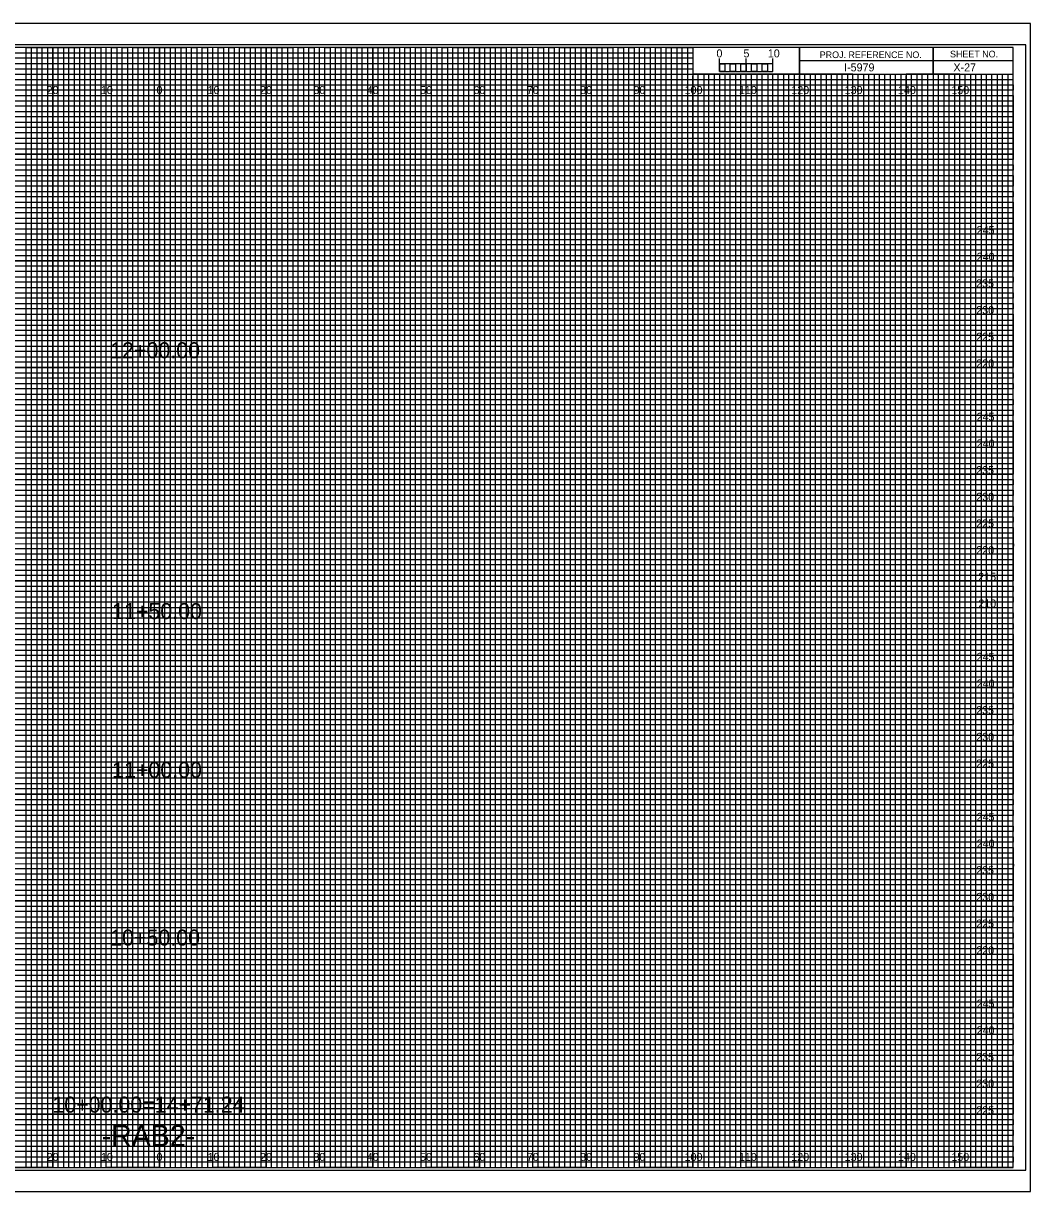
# Model space of a CAD drawing. Extents: x -13 to 323, y -5 to 654.
# Drawn here: x 134.5 to 323.3, y -4.5 to 214.5 of the extents above; entities that cross this region are included whole.
import ezdxf

# ---------------------------------------------------------------- set-up
doc = ezdxf.new("R2010")
doc.units = 0
for name, color, linetype in [('Exist CMT Pavement', 7, 'Continuous'), ('Exist Cross Section Cell', 7, 'Continuous'), ('Exist XS Center Line Elevation Label', 7, 'Continuous'), ('Exist XS Ground Line', 7, 'Continuous'), ('Prop CMT Conc Surface', 7, 'Continuous'), ('Prop CMT Concrete Structures', 7, 'Continuous'), ('Prop CMT DNC', 7, 'Continuous'), ('Prop CMT Pvmt Course 1 CG', 7, 'Continuous'), ('Prop CMT Pvmt Course 1 Wedge', 7, 'Continuous'), ('Prop CMT Pvmt Course 2', 7, 'Continuous'), ('Prop CMT Pvmt Course 2 Wedge', 7, 'Continuous'), ('Prop CMT Pvmt Course 3', 7, 'Continuous'), ('Prop CMT Pvmt Course 3 Wedge', 7, 'Continuous'), ('Prop CMT Pvmt Surface', 7, 'Continuous'), ('Prop CMT Shear Line', 7, 'Continuous'), ('Prop CMT Slope Grass', 7, 'Continuous'), ('Prop CMT Subgrade Earthwork', 7, 'Continuous')]:
    doc.layers.add(name, color=color, linetype=linetype)

msp = doc.modelspace()

# ---------------------------------------------------------------- linework, layer by layer
at = {"layer": 'Exist XS Center Line Elevation Label'}
for points in [[(125, 0), (135, 0), (135, 210), (145, 210), (145, 0), (155, 0), (155, 210), (165, 210), (165, 0), (175, 0), (175, 210), (185, 210), (185, 0), (195, 0), (195, 210), (205, 210), (205, 0), (215, 0), (215, 210), (225, 210), (225, 0), (235, 0), (235, 210), (245, 210), (245, 0), (255, 0), (255, 210), (259.93, 210), (260, 210), (260, 205), (264.99, 205), (264.99, 0), (275, 0), (275, 205), (285, 205), (285, 0), (295, 0), (295, 205), (305, 205), (305, 0), (315, 0), (315, 205)], [(0, 205), (275, 205)], [(0, 185), (320, 185), (320, 195), (0, 195)], [(0, 165), (320, 165), (320, 175), (0, 175)], [(0, 145), (320, 145), (320, 155), (0, 155)], [(0, 125), (320, 125), (320, 135), (0, 135)], [(0, 105), (320, 105), (320, 115), (0, 115)], [(0, 85), (320, 85), (320, 95), (0, 95)], [(0, 65), (320, 65), (320, 75), (0, 75)], [(0, 45), (320, 45), (320, 55), (0, 55)], [(0, 25), (320, 25), (320, 35), (0, 35)], [(0, 5), (320, 5), (320, 15), (0, 15)]]:
    msp.add_lwpolyline(points, dxfattribs=at)
at = {"layer": 'Exist XS Ground Line'}
for p, q in [((150, 210), (140, 210)), ((140, 210), (140, 0)), ((150, 0), (150, 210)), ((170, 210), (160, 210)), ((160, 210), (160, 0)), ((170, 0), (170, 210)), ((190, 210), (180, 210)), ((180, 210), (180, 0)), ((190, 0), (190, 210)), ((210, 210), (200, 210)), ((200, 210), (200, 0)), ((210, 0), (210, 210)), ((230, 210), (220, 210)), ((220, 210), (220, 0)), ((230, 0), (230, 210)), ((250, 210), (240, 210)), ((240, 210), (240, 0)), ((250, 0), (250, 210)), ((260, 210), (260, 0)), ((270, 0), (270, 205)), ((290, 205), (280, 205)), ((280, 205), (280, 0)), ((290, 0), (290, 205)), ((310, 205), (300, 205)), ((300, 205), (300, 0)), ((310, 0), (310, 205)), ((140, 0), (130, 0)), ((160, 0), (150, 0)), ((180, 0), (170, 0)), ((200, 0), (190, 0)), ((220, 0), (210, 0)), ((240, 0), (230, 0)), ((260, 0), (250, 0)), ((280, 0), (270, 0)), ((300, 0), (290, 0)), ((320, 0), (310, 0)), ((320, 0), (320, 0))]:
    msp.add_line(p, q, dxfattribs=at)
for points in [[(0, 200), (320, 200), (320, 190), (0, 190)], [(0, 180), (320, 180), (320, 170), (0, 170)], [(0, 160), (320, 160), (320, 150), (0, 150)], [(0, 140), (320, 140), (320, 130), (0, 130)], [(0, 120), (320, 120), (320, 110), (0, 110)], [(0, 100), (320, 100), (320, 90), (0, 90)], [(0, 80), (320, 80), (320, 70), (0, 70)], [(0, 60), (320, 60), (320, 50), (0, 50)], [(0, 40), (320, 40), (320, 30), (0, 30)], [(0, 20), (320, 20), (320, 10), (0, 10)]]:
    msp.add_lwpolyline(points, dxfattribs=at)
at = {"layer": 'Prop CMT Conc Surface'}
msp.add_lwpolyline([(-13.4, -4.5), (323.3, -4.5), (323.3, 214.5), (-13.4, 214.5)], close=True, dxfattribs=at)
at = {"layer": 'Prop CMT Concrete Structures'}
for p, q in [((305, 210), (305, 205)), ((305, 205), (305, 210)), ((280, 207.5), (280, 205)), ((320, 207.49), (280, 207.49)), ((280, 205), (320, 205))]:
    msp.add_line(p, q, dxfattribs=at)
for points in [[(320, 210), (0, 210), (0, 0), (320, 0)], [(280, 210), (260, 210), (260, 205.03), (280, 205.03)], [(320, 210), (280, 210), (280, 205), (320, 205)]]:
    msp.add_lwpolyline(points, close=True, dxfattribs=at)
at = {"layer": 'Prop CMT DNC'}
for p, q in [((267, 205), (266.01, 205)), ((266.01, 205), (266.01, 0)), ((267, 0), (267, 205)), ((269, 205), (268, 205)), ((268, 205), (268, 0)), ((269, 0), (269, 205)), ((266.01, 0), (265, 0)), ((268, 0), (267, 0))]:
    msp.add_line(p, q, dxfattribs=at)
for points in [[(135, 0), (136, 0), (136, 210), (137, 210), (137, 0)], [(137, 0), (138, 0), (138, 210), (139, 210), (139, 0)], [(140, 0), (141, 0), (141, 210), (142, 210), (142, 0)], [(142, 0), (143, 0), (143, 210), (144, 210), (144, 0)], [(145, 0), (146, 0), (146, 210), (147, 210), (147, 0)], [(147, 0), (148, 0), (148, 210), (149, 210), (149, 0)], [(150, 0), (151, 0), (151, 210), (152, 210), (152, 0)], [(152, 0), (153, 0), (153, 210), (154, 210), (154, 0)], [(155, 0), (156, 0), (156, 210), (157, 210), (157, 0)], [(157, 0), (158, 0), (158, 210), (159, 210), (159, 0)], [(160, 0), (161, 0), (161, 210), (162, 210), (162, 0)], [(162, 0), (163, 0), (163, 210), (164, 210), (164, 0)], [(165, 0), (166, 0), (166, 210), (167, 210), (167, 0)], [(167, 0), (168, 0), (168, 210), (169, 210), (169, 0)], [(170, 0), (171, 0), (171, 210), (172, 210), (172, 0)], [(172, 0), (173, 0), (173, 210), (174, 210), (174, 0)], [(175, 0), (176, 0), (176, 210), (177, 210), (177, 0)], [(177, 0), (178, 0), (178, 210), (179, 210), (179, 0)], [(180, 0), (181, 0), (181, 210), (182, 210), (182, 0)], [(182, 0), (183, 0), (183, 210), (184, 210), (184, 0)], [(185, 0), (186, 0), (186, 210), (187, 210), (187, 0)], [(187, 0), (188, 0), (188, 210), (189, 210), (189, 0)], [(190, 0), (191, 0), (191, 210), (192, 210), (192, 0)], [(192, 0), (193, 0), (193, 210), (194, 210), (194, 0)], [(195, 0), (196, 0), (196, 210), (197, 210), (197, 0)], [(197, 0), (198, 0), (198, 210), (199, 210), (199, 0)], [(200, 0), (201, 0), (201, 210), (202, 210), (202, 0)], [(202, 0), (203, 0), (203, 210), (204, 210), (204, 0)], [(205, 0), (206, 0), (206, 210), (207, 210), (207, 0)], [(207, 0), (208, 0), (208, 210), (209, 210), (209, 0)], [(210, 0), (211, 0), (211, 210), (212, 210), (212, 0)], [(212, 0), (213, 0), (213, 210), (214, 210), (214, 0)], [(215, 0), (216, 0), (216, 210), (217, 210), (217, 0)], [(217, 0), (218, 0), (218, 210), (219, 210), (219, 0)], [(220, 0), (221, 0), (221, 210), (222, 210), (222, 0)], [(222, 0), (223, 0), (223, 210), (224, 210), (224, 0)], [(225, 0), (226, 0), (226, 210), (227, 210), (227, 0)], [(227, 0), (228, 0), (228, 210), (229, 210), (229, 0)], [(230, 0), (231, 0), (231, 210), (232, 210), (232, 0)], [(232, 0), (233, 0), (233, 210), (234, 210), (234, 0)], [(235, 0), (236, 0), (236, 210), (237, 210), (237, 0)], [(237, 0), (238, 0), (238, 210), (239, 210), (239, 0)], [(240, 0), (241, 0), (241, 210), (242, 210), (242, 0)], [(242, 0), (243, 0), (243, 210), (244, 210), (244, 0)], [(245, 0), (246, 0), (246, 210), (247, 210), (247, 0)], [(247, 0), (248, 0), (248, 210), (249, 210), (249, 0)], [(250, 0), (251, 0), (251, 210), (252, 210), (252, 0)], [(252, 0), (253, 0), (253, 210), (254, 210), (254, 0)], [(255, 0), (256, 0), (256, 210), (257, 210), (257, 0)], [(257, 0), (258, 0), (258, 210), (259, 210), (259, 0)], [(260, 0), (261, 0), (261, 205), (262.02, 205), (262.02, 0)], [(262, 0), (263, 0), (263, 205), (263.99, 205), (263.99, 0)], [(270, 0), (270.98, 0), (270.98, 205), (272, 205), (272, 0)], [(272, 0), (273, 0), (273, 205), (274.05, 205), (274.05, 0)], [(275, 0), (276, 0), (276, 205), (277, 205), (277, 0)], [(277, 0), (278, 0), (278, 205), (279, 205), (279, 0)], [(280, 0), (281, 0), (281, 205), (282, 205), (282, 0)], [(282, 0), (283, 0), (283, 205), (284, 205), (284, 0)], [(285, 0), (286, 0), (286, 205), (287, 205), (287, 0)], [(287, 0), (288, 0), (288, 205), (289, 205), (289, 0)], [(290, 0), (291, 0), (291, 205), (292, 205), (292, 0)], [(292, 0), (293, 0), (293, 205), (294, 205), (294, 0)], [(295, 0), (296, 0), (296, 205), (297, 205), (297, 0)], [(297, 0), (298, 0), (298, 205), (299, 205), (299, 0)], [(300, 0), (301, 0), (301, 205), (302, 205), (302, 0)], [(302, 0), (303, 0), (303, 205), (304, 205), (304, 0)], [(305, 0), (306, 0), (306, 205), (307, 205), (307, 0)], [(307, 0), (308, 0), (308, 205), (309, 205), (309, 0)], [(310, 0), (311, 0), (311, 205), (312, 205), (312, 0)], [(312, 0), (313, 0), (313, 205), (314, 205), (314, 0)], [(315, 0), (316, 0), (316, 205), (317, 205), (317, 0)], [(317, 0), (318, 0), (318, 205), (319, 205), (319, 0)]]:
    msp.add_lwpolyline(points, dxfattribs=at)
at = {"layer": 'Prop CMT Pvmt Course 1 Wedge'}
for p, q in [((323.3, 214.5), (-13.4, 214.5)), ((-13.4, -4.5), (323.3, -4.5))]:
    msp.add_line(p, q, dxfattribs=at)
at = {"layer": 'Prop CMT Pvmt Course 2'}
msp.add_lwpolyline([(-10.8, -0.5), (322.4, -0.5), (322.4, 210.5), (-10.8, 210.5)], close=True, dxfattribs=at)
at = {"layer": 'Prop CMT Pvmt Course 3'}
for p, q in [((140, 0), (140, 210)), ((150, 0), (150, 210)), ((160, 0), (160, 210)), ((170, 0), (170, 210)), ((180, 0), (180, 210)), ((190, 0), (190, 210)), ((200, 0), (200, 210)), ((210, 0), (210, 210)), ((220, 0), (220, 210)), ((230, 0), (230, 210)), ((240, 0), (240, 210)), ((250, 0), (250, 210)), ((260, 0), (260, 204.69)), ((270, 0), (270, 204.69)), ((280, 0), (280, 204.69)), ((290, 0), (290, 204.69)), ((300, 0), (300, 204.69)), ((310, 0), (310, 204.69)), ((0, 200), (320, 200)), ((0, 190), (320, 190)), ((0, 180), (320, 180)), ((0, 170), (320, 170)), ((0, 160), (320, 160)), ((0, 150), (320, 150)), ((0, 140), (320, 140)), ((0, 130), (320, 130)), ((0, 120), (320, 120)), ((0, 110), (320, 110)), ((0, 100), (320, 100)), ((0, 90), (320, 90)), ((0, 80), (320, 80)), ((0, 70), (320, 70)), ((0, 60), (320, 60)), ((0, 50), (320, 50)), ((0, 40), (320, 40)), ((0, 30), (320, 30)), ((0, 20), (320, 20)), ((0, 10), (320, 10))]:
    msp.add_line(p, q, dxfattribs=at)
at = {"layer": 'Prop CMT Slope Grass'}
for p, q in [((265, 205.49), (265, 207.9)), ((265, 206.9), (265, 207.9)), ((270, 205.49), (270, 207.9)), ((275, 205.49), (275, 207.9)), ((275, 206.9), (275, 207.9))]:
    msp.add_line(p, q, dxfattribs=at)
for points in [[(275, 206.9), (265, 206.9), (265, 205.49), (275, 205.49)], [(265, 206.9), (266, 206.9), (266, 205.49), (265, 205.49)], [(267, 206.9), (268, 206.9), (268, 205.49), (267, 205.49)], [(269, 206.9), (270, 206.9), (270, 205.49), (269, 205.49)], [(271, 206.9), (272, 206.9), (272, 205.49), (271, 205.49)], [(273, 206.9), (274, 206.9), (274, 205.49), (273, 205.49)]]:
    msp.add_lwpolyline(points, close=True, dxfattribs=at)
at = {"layer": 'Prop CMT Subgrade Earthwork'}
for p, q in [((0, 209), (260, 209)), ((260, 209), (260, 207.98)), ((260, 207.98), (0, 207.98)), ((0, 207), (260, 207)), ((260, 205.89), (0, 205.89)), ((260, 207), (260, 205.89)), ((0, 204), (320, 204))]:
    msp.add_line(p, q, dxfattribs=at)
for points in [[(0, 203), (270, 203), (320, 203), (320, 202), (0, 202)], [(0, 201), (320, 201), (320, 199), (0, 199)], [(0, 198), (320, 198), (320, 197), (0, 196.98)], [(0, 196), (320, 196), (320, 194), (0, 194)], [(0, 193), (320, 193), (320, 192), (0, 192)], [(0, 191), (320, 191), (320, 189), (0, 189)], [(0, 188), (320, 188), (320, 187), (0, 187)], [(0, 186), (320, 186), (320, 184), (0, 184)], [(0, 183), (320, 183), (320, 182), (0, 182)], [(0, 181), (320, 181), (320, 179), (0, 179)], [(0, 178), (320, 178), (320, 177), (0, 177)], [(0, 176), (320, 176), (320, 173.95), (320, 173), (320, 172), (0, 172)], [(0, 174), (320, 174), (320, 173), (0, 173)], [(0, 171), (320, 171), (320, 169), (0, 169.03)], [(0, 169.03), (320, 169), (320, 168), (0, 168)], [(0, 167), (320, 167), (320, 166), (0, 166)], [(0, 164), (320, 164), (320, 163), (0, 163)], [(0, 162), (320, 162), (320, 161), (0, 161)], [(-0.07, 158.89), (320, 158.89), (320, 157.88), (-0.07, 157.88)], [(0, 157), (320, 157), (320, 156), (0, 156)], [(0, 154), (320, 154), (320, 153), (0, 153)], [(0, 152), (320, 152), (320, 151), (0, 151)], [(0, 149), (320, 149), (320, 148), (0, 148)], [(0, 147), (320, 147), (320, 146), (0, 146)], [(0, 144), (320, 144), (320, 143), (0, 143)], [(0, 142), (320, 142), (320, 141), (0, 141)], [(0, 139), (320, 139), (319.99, 137.98), (0, 138)], [(0, 137), (320, 137), (320, 136), (0, 136)], [(0, 134), (320, 134), (320, 133), (0, 133)], [(0, 132), (320, 132), (320, 131), (0, 131)], [(0, 129), (320, 129), (320, 128), (0, 128)], [(0, 127), (320, 127), (320, 126), (0, 126)], [(0, 124), (320, 124), (320, 123), (0, 123)], [(0, 122), (320, 122), (320, 121), (0, 121)], [(0, 119), (320, 119), (320, 118), (0, 118)], [(0, 116.99), (320.07, 116.91), (320, 116), (0, 116)], [(0, 114), (320, 114), (320, 113), (0, 113)], [(0, 112), (320, 112), (320, 111), (0, 111)], [(0, 109), (320, 109), (320, 108), (0, 108)], [(0, 107), (320, 107), (320, 106), (0, 106)], [(0, 104), (320, 104), (320, 103), (0, 103)], [(0, 102), (320, 102), (320, 101), (0, 101)], [(0, 99), (320, 99), (320, 98), (0, 98)], [(0, 97), (320, 97), (320, 96), (0, 96)], [(0, 94), (320, 94), (320, 93), (0, 93)], [(0, 92), (320, 92), (320, 91), (0, 91)], [(0, 89), (320, 89), (320, 88), (0, 88)], [(0, 87), (320, 87), (320, 86), (0, 86)], [(0, 84), (320, 84), (320, 83), (0, 83)], [(0, 82), (320, 82), (320, 81), (0, 81)], [(0, 79), (320, 79), (319.99, 77.98), (0, 78)], [(0, 77), (320, 77), (320, 76), (0, 76)], [(0, 74), (320, 74), (320, 73), (0, 73)], [(0, 72), (320, 72), (320, 71), (0, 71)], [(0, 69), (320, 69), (320, 68), (0, 68)], [(0, 67), (320, 67), (320, 66), (0, 66)], [(0, 64), (320, 64), (320, 63), (0, 63)], [(0, 62), (320, 62), (320, 61), (0, 61)], [(0, 59), (320, 59), (320, 58), (0, 58)], [(0, 56.99), (320.07, 56.91), (320, 56), (0, 56)], [(0, 54), (320, 54), (320, 53), (0, 53)], [(0, 52), (320, 52), (320, 51), (0, 51)], [(0, 49), (320, 49), (320, 48), (0, 48)], [(0, 47), (320, 47), (320, 46), (0, 46)], [(0, 44), (320, 44), (320, 43), (0, 43)], [(0, 42), (320, 42), (320, 41), (0, 41)], [(0, 39), (320, 39), (320, 38), (0, 38)], [(0, 37), (320, 37), (320, 36), (0, 36)], [(0, 34), (320, 34), (320, 33), (0, 33)], [(0, 32), (320, 32), (320, 31), (0, 31)], [(0, 29), (320, 29), (320, 28), (0, 28)], [(0, 27), (320, 27), (320, 26), (0, 26)], [(0, 24), (320, 24), (320, 23), (0, 23)], [(0, 22), (320, 22), (320, 21), (0, 21)], [(0, 19), (320, 19), (320, 18), (0, 18)], [(0, 17), (320, 17), (320, 16), (0, 16)], [(0, 14), (320, 14), (320, 13), (0, 13)], [(0, 12), (320, 12), (320, 11), (0, 11)], [(0, 9), (320, 9), (320, 8), (0, 8)], [(0, 7), (320, 7), (320, 6), (0, 6)], [(0, 4), (320, 4), (320, 3), (0, 3)], [(0, 2), (320, 2), (320, 1), (0, 1)]]:
    msp.add_lwpolyline(points, dxfattribs=at)

# ---------------------------------------------------------------- texts
at = {"layer": 'Exist CMT Pavement'}
msp.add_text('I-5979', height=1.5, dxfattribs=at).set_placement((288.34, 205.5))
at = {"layer": 'Exist Cross Section Cell'}
for s, p in [('20', (138.86, 201.25)), ('10', (149.04, 201.25)), ('0', (159.45, 201.25)), ('0', (159.45, 201.25)), ('10', (169.04, 201.25)), ('20', (178.86, 201.25)), ('30', (188.86, 201.25)), ('40', (198.86, 201.25)), ('50', (208.86, 201.25)), ('60', (218.86, 201.25)), ('70', (228.86, 201.25)), ('80', (238.86, 201.25)), ('90', (248.86, 201.25)), ('100', (258.44, 201.25)), ('110', (268.62, 201.25)), ('120', (278.44, 201.25)), ('130', (288.44, 201.25)), ('140', (298.44, 201.25)), ('150', (308.44, 201.25)), ('20', (138.86, 1.25)), ('10', (149.04, 1.25)), ('0', (159.45, 1.25)), ('0', (159.45, 1.25)), ('10', (169.04, 1.25)), ('20', (178.86, 1.25)), ('30', (188.86, 1.25)), ('40', (198.86, 1.25)), ('50', (208.86, 1.25)), ('60', (218.86, 1.25)), ('70', (228.86, 1.25)), ('80', (238.86, 1.25)), ('90', (248.86, 1.25)), ('100', (258.44, 1.25)), ('110', (268.62, 1.25)), ('120', (278.44, 1.25)), ('130', (288.44, 1.25)), ('140', (298.44, 1.25)), ('150', (308.44, 1.25))]:
    msp.add_text(s, height=1.5, dxfattribs=at).set_placement(p)
at = {"layer": 'Prop CMT Concrete Structures'}
for s, p in [('PROJ. REFERENCE NO.', (283.77, 207.99)), ('SHEET NO.', (308.19, 208.12))]:
    msp.add_text(s, height=1.25, dxfattribs=at).set_placement(p)
at = {"layer": 'Prop CMT Pvmt Course 1 CG'}
for s, p in [('5', (269.47, 208.12)), ('10', (274.04, 208.12))]:
    msp.add_text(s, height=1.5, dxfattribs=at).set_placement(p)
at = {"layer": 'Prop CMT Pvmt Course 2 Wedge'}
for s, p in [('245', (313.18, 175)), ('240', (313.19, 170)), ('235', (313.09, 165)), ('230', (313.11, 160)), ('225', (313.1, 155)), ('220', (313.12, 150)), ('245', (313.18, 140)), ('240', (313.19, 135)), ('235', (313.09, 130)), ('230', (313.11, 125)), ('225', (313.1, 120)), ('220', (313.12, 115)), ('215', (313.48, 110)), ('210', (313.5, 105)), ('245', (313.18, 95)), ('240', (313.19, 90)), ('235', (313.09, 85)), ('230', (313.11, 80)), ('225', (313.1, 75)), ('245', (313.18, 65)), ('240', (313.19, 60)), ('235', (313.09, 55)), ('230', (313.11, 50)), ('225', (313.1, 45)), ('220', (313.12, 40)), ('245', (313.18, 30)), ('240', (313.19, 25)), ('235', (313.09, 20)), ('230', (313.11, 15)), ('225', (313.1, 10))]:
    msp.add_text(s, height=1.5, dxfattribs=at).set_placement(p)
at = {"layer": 'Prop CMT Pvmt Course 3 Wedge'}
for s, p in [('12+00.00', (150.77, 151.72)), ('11+50.00', (151.13, 102.83)), ('11+00.00', (151.13, 73.06)), ('10+50.00', (150.77, 41.62)), ('10+00.00=14+71.24', (139.93, 10.31))]:
    msp.add_text(s, height=3, dxfattribs=at).set_placement(p)
at = {"layer": 'Prop CMT Pvmt Surface'}
msp.add_text('-RAB2-', height=4, dxfattribs=at).set_placement((149.17, 4))
at = {"layer": 'Prop CMT Shear Line'}
msp.add_text('X-27', height=1.5, dxfattribs=at).set_placement((308.83, 205.5))
at = {"layer": 'Prop CMT Slope Grass'}
msp.add_text('0', height=1.5, dxfattribs=at).set_placement((264.41, 208.12))

doc.saveas('drawing.dxf')
